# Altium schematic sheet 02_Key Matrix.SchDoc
size 464 x 203 mm
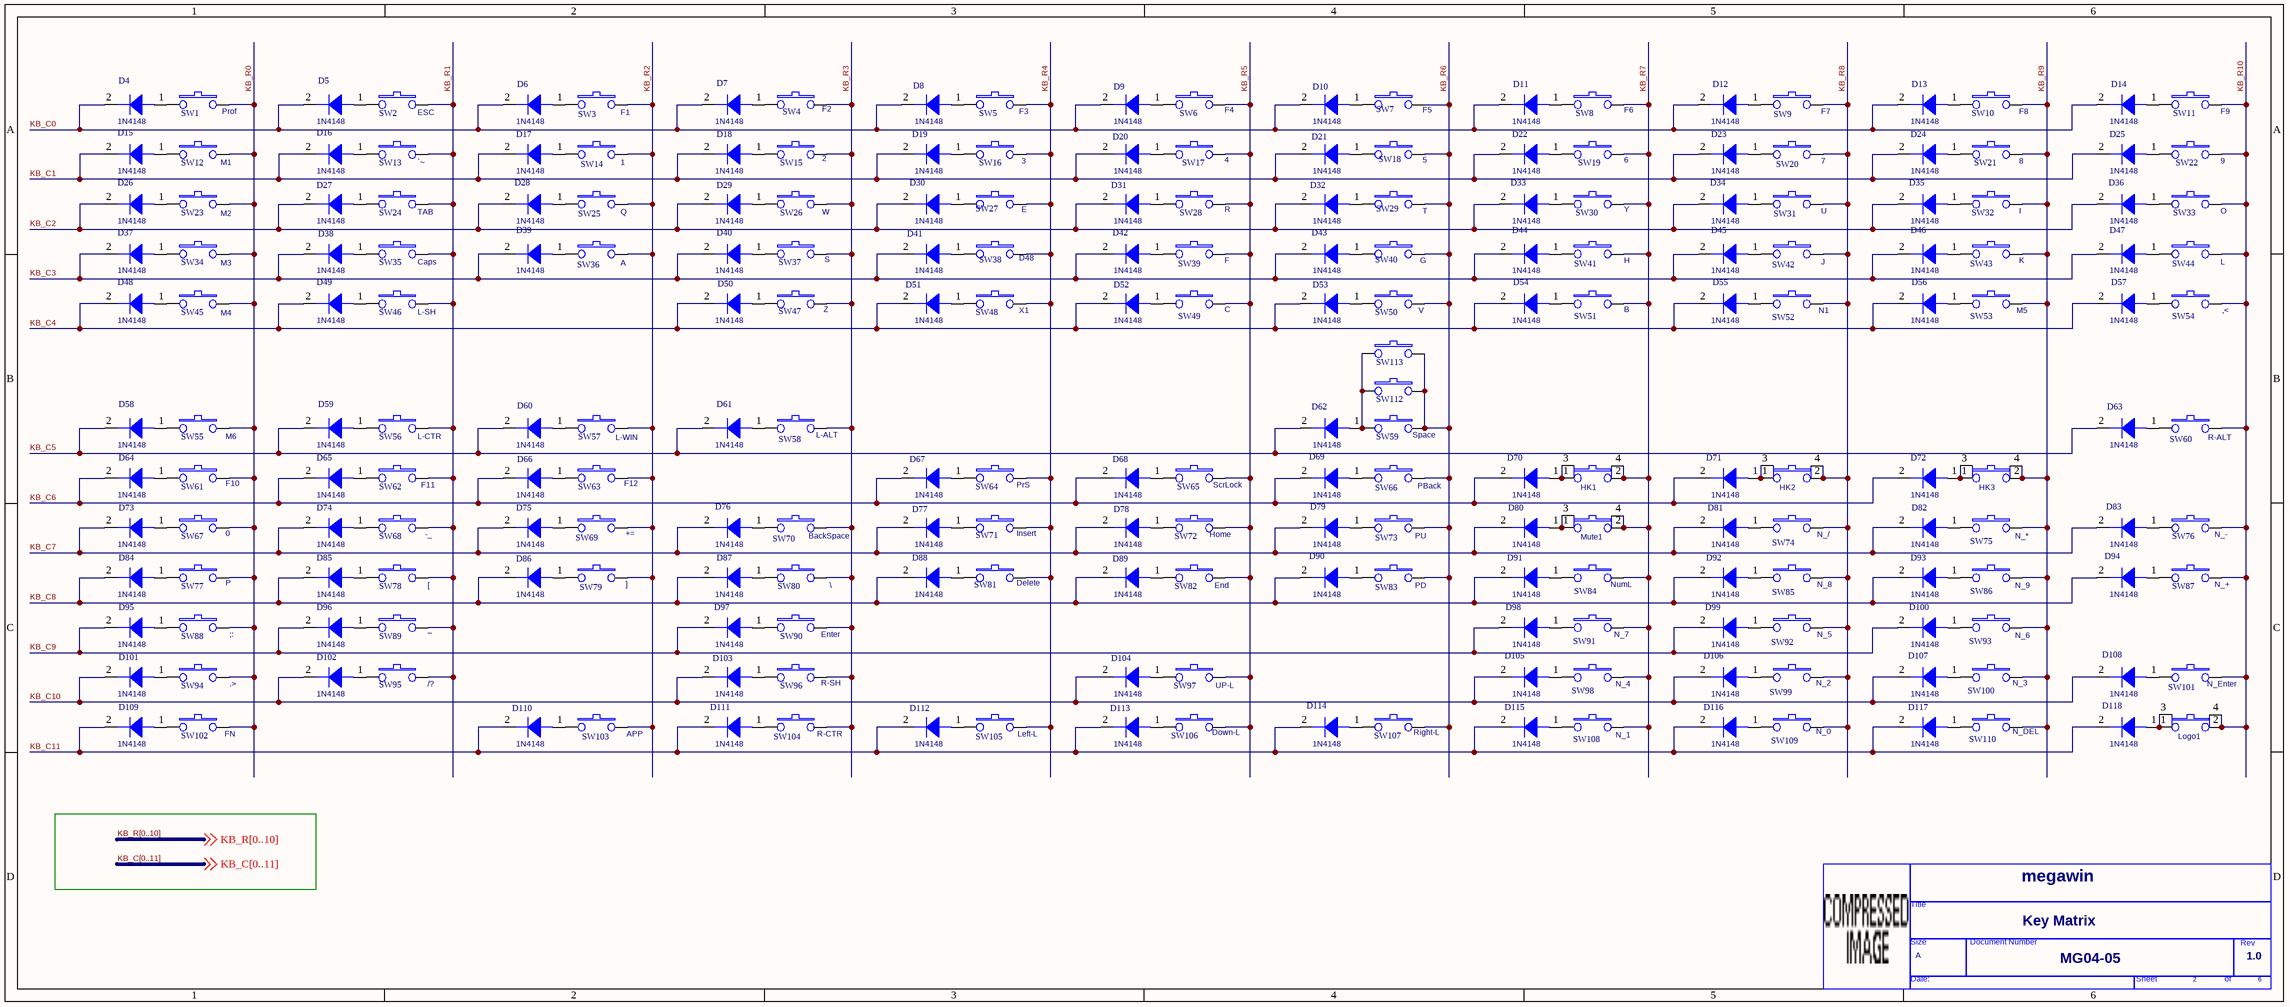
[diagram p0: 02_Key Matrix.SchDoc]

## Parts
*  OrgName: megawin  Doc: MG04-05  RevCode: 1.0  Title: Key Matrix  Page Size: A  Page Number: 2  Page Count: 6  (hidden comment: TitleBlock_MegaWin)  (graphical)
D4  1N4148  [DIODE_DO213AA]
D5  1N4148  [DIODE_DO213AA]
D6  1N4148  [DIODE_DO213AA]
D7  1N4148  [DIODE_DO213AA]
D8  1N4148  [DIODE_DO213AA]
D9  1N4148  [DIODE_DO213AA]
D10  1N4148  [DIODE_DO213AA]
D11  1N4148  [DIODE_DO213AA]
D12  1N4148  [DIODE_DO213AA]
D13  1N4148  [DIODE_DO213AA]
D14  1N4148  [DIODE_DO213AA]
D15  1N4148  [DIODE_DO213AA]
D16  1N4148  [DIODE_DO213AA]
D17  1N4148  [DIODE_DO213AA]
D18  1N4148  [DIODE_DO213AA]
D19  1N4148  [DIODE_DO213AA]
D20  1N4148  [DIODE_DO213AA]
D21  1N4148  [DIODE_DO213AA]
D22  1N4148  [DIODE_DO213AA]
D23  1N4148  [DIODE_DO213AA]
D24  1N4148  [DIODE_DO213AA]
D25  1N4148  [DIODE_DO213AA]
D26  1N4148  [DIODE_DO213AA]
D27  1N4148  [DIODE_DO213AA]
D28  1N4148  [DIODE_DO213AA]
D29  1N4148  [DIODE_DO213AA]
D30  1N4148  [DIODE_DO213AA]
D31  1N4148  [DIODE_DO213AA]
D32  1N4148  [DIODE_DO213AA]
D33  1N4148  [DIODE_DO213AA]
D34  1N4148  [DIODE_DO213AA]
D35  1N4148  [DIODE_DO213AA]
D36  1N4148  [DIODE_DO213AA]
D37  1N4148  [DIODE_DO213AA]
D38  1N4148  [DIODE_DO213AA]
D39  1N4148  [DIODE_DO213AA]
D40  1N4148  [DIODE_DO213AA]
D41  1N4148  [DIODE_DO213AA]
D42  1N4148  [DIODE_DO213AA]
D43  1N4148  [DIODE_DO213AA]
D44  1N4148  [DIODE_DO213AA]
D45  1N4148  [DIODE_DO213AA]
D46  1N4148  [DIODE_DO213AA]
D47  1N4148  [DIODE_DO213AA]
D48  1N4148  [DIODE_DO213AA]
D49  1N4148  [DIODE_DO213AA]
D50  1N4148  [DIODE_DO213AA]
D51  1N4148  [DIODE_DO213AA]
D52  1N4148  [DIODE_DO213AA]
D53  1N4148  [DIODE_DO213AA]
D54  1N4148  [DIODE_DO213AA]
D55  1N4148  [DIODE_DO213AA]
D56  1N4148  [DIODE_DO213AA]
D57  1N4148  [DIODE_DO213AA]
D58  1N4148  [DIODE_DO213AA]
D59  1N4148  [DIODE_DO213AA]
D60  1N4148  [DIODE_DO213AA]
D61  1N4148  [DIODE_DO213AA]
D62  1N4148  [DIODE_DO213AA]
D63  1N4148  [DIODE_DO213AA]
D64  1N4148  [DIODE_DO213AA]
D65  1N4148  [DIODE_DO213AA]
D66  1N4148  [DIODE_DO213AA]
D67  1N4148  [DIODE_DO213AA]
D68  1N4148  [DIODE_DO213AA]
D69  1N4148  [DIODE_DO213AA]
D70  1N4148  [DIODE_DO213AA]
D71  1N4148  [DIODE_DO213AA]
D72  1N4148  [DIODE_DO213AA]
D73  1N4148  [DIODE_DO213AA]
D74  1N4148  [DIODE_DO213AA]
D75  1N4148  [DIODE_DO213AA]
D76  1N4148  [DIODE_DO213AA]
D77  1N4148  [DIODE_DO213AA]
D78  1N4148  [DIODE_DO213AA]
D79  1N4148  [DIODE_DO213AA]
D80  1N4148  [DIODE_DO213AA]
D81  1N4148  [DIODE_DO213AA]
D82  1N4148  [DIODE_DO213AA]
D83  1N4148  [DIODE_DO213AA]
D84  1N4148  [DIODE_DO213AA]
D85  1N4148  [DIODE_DO213AA]
D86  1N4148  [DIODE_DO213AA]
D87  1N4148  [DIODE_DO213AA]
D88  1N4148  [DIODE_DO213AA]
D89  1N4148  [DIODE_DO213AA]
D90  1N4148  [DIODE_DO213AA]
D91  1N4148  [DIODE_DO213AA]
D92  1N4148  [DIODE_DO213AA]
D93  1N4148  [DIODE_DO213AA]
D94  1N4148  [DIODE_DO213AA]
D95  1N4148  [DIODE_DO213AA]
D96  1N4148  [DIODE_DO213AA]
D97  1N4148  [DIODE_DO213AA]
D98  1N4148  [DIODE_DO213AA]
D99  1N4148  [DIODE_DO213AA]
D100  1N4148  [DIODE_DO213AA]
D101  1N4148  [DIODE_DO213AA]
D102  1N4148  [DIODE_DO213AA]
D103  1N4148  [DIODE_DO213AA]
D104  1N4148  [DIODE_DO213AA]
D105  1N4148  [DIODE_DO213AA]
D106  1N4148  [DIODE_DO213AA]
D107  1N4148  [DIODE_DO213AA]
D108  1N4148  [DIODE_DO213AA]
D109  1N4148  [DIODE_DO213AA]
D110  1N4148  [DIODE_DO213AA]
D111  1N4148  [DIODE_DO213AA]
D112  1N4148  [DIODE_DO213AA]
D113  1N4148  [DIODE_DO213AA]
D114  1N4148  [DIODE_DO213AA]
D115  1N4148  [DIODE_DO213AA]
D116  1N4148  [DIODE_DO213AA]
D117  1N4148  [DIODE_DO213AA]
D118  1N4148  [DIODE_DO213AA]
HK1  SW-PB-4P  [SW-TACT-P4.5X6.5-Z6.2X6.2X5]  (value not drawn)
HK2  SW-PB-4P  [SW-TACT-P4.5X6.5-Z6.2X6.2X5]  (value not drawn)
HK3  SW-PB-4P  [SW-TACT-P4.5X6.5-Z6.2X6.2X5]  (value not drawn)
Logo1  SW-PB-4P  [SW-TACT-P4.5X6.5-Z6.2X6.2X5]  (value not drawn)
Mute1  SW-PB-4P  [SW-TACT-P4.5X6.5-Z6.2X6.2X5]  (value not drawn)
SW1  Function: Prof  [SW2_KS4B]  (hidden comment: SW_PB_SPST)
SW2  Function: ESC  [SW2_KS4B]  (hidden comment: SW_PB_SPST)
SW3  Function: F1  [SW2_KS4B]  (hidden comment: SW_PB_SPST)
SW4  Function: F2  [SW2_KS4B]  (hidden comment: SW_PB_SPST)
SW5  Function: F3  [SW2_KS4B]  (hidden comment: SW_PB_SPST)
SW6  Function: F4  [SW2_KS4B]  (hidden comment: SW_PB_SPST)
SW7  Function: F5  [SW2_KS4B]  (hidden comment: SW_PB_SPST)
SW8  Function: F6  [SW2_KS4B]  (hidden comment: SW_PB_SPST)
SW9  Function: F7  [SW2_KS4B]  (hidden comment: SW_PB_SPST)
SW10  Function: F8  [SW2_KS4B]  (hidden comment: SW_PB_SPST)
SW11  Function: F9  [SW2_KS4B]  (hidden comment: SW_PB_SPST)
SW12  Function: M1  [SW2_KS4B]  (hidden comment: SW_PB_SPST)
SW13  Function: `~  [SW2_KS4B]  (hidden comment: SW_PB_SPST)
SW14  Function: 1  [SW2_KS4B]  (hidden comment: SW_PB_SPST)
SW15  Function: 2  [SW2_KS4B]  (hidden comment: SW_PB_SPST)
SW16  Function: 3  [SW2_KS4B]  (hidden comment: SW_PB_SPST)
SW17  Function: 4  [SW2_KS4B]  (hidden comment: SW_PB_SPST)
SW18  Function: 5  [SW2_KS4B]  (hidden comment: SW_PB_SPST)
SW19  Function: 6  [SW2_KS4B]  (hidden comment: SW_PB_SPST)
SW20  Function: 7  [SW2_KS4B]  (hidden comment: SW_PB_SPST)
SW21  Function: 8  [SW2_KS4B]  (hidden comment: SW_PB_SPST)
SW22  Function: 9  [SW2_KS4B]  (hidden comment: SW_PB_SPST)
SW23  Function: M2  [SW2_KS4B]  (hidden comment: SW_PB_SPST)
SW24  Function: TAB  [SW2_KS4B]  (hidden comment: SW_PB_SPST)
SW25  Function: Q  [SW2_KS4B]  (hidden comment: SW_PB_SPST)
SW26  Function: W  [SW2_KS4B]  (hidden comment: SW_PB_SPST)
SW27  Function: E  [SW2_KS4B]  (hidden comment: SW_PB_SPST)
SW28  Function: R  [SW2_KS4B]  (hidden comment: SW_PB_SPST)
SW29  Function: T  [SW2_KS4B]  (hidden comment: SW_PB_SPST)
SW30  Function: Y  [SW2_KS4B]  (hidden comment: SW_PB_SPST)
SW31  Function: U  [SW2_KS4B]  (hidden comment: SW_PB_SPST)
SW32  Function: I  [SW2_KS4B]  (hidden comment: SW_PB_SPST)
SW33  Function: O  [SW2_KS4B]  (hidden comment: SW_PB_SPST)
SW34  Function: M3  [SW2_KS4B]  (hidden comment: SW_PB_SPST)
SW35  Function: Caps  [SW2_KS4B]  (hidden comment: SW_PB_SPST)
SW36  Function: A  [SW2_KS4B]  (hidden comment: SW_PB_SPST)
SW37  Function: S  [SW2_KS4B]  (hidden comment: SW_PB_SPST)
SW38  Function: D48  [SW2_KS4B]  (hidden comment: SW_PB_SPST)
SW39  Function: F  [SW2_KS4B]  (hidden comment: SW_PB_SPST)
SW40  Function: G  [SW2_KS4B]  (hidden comment: SW_PB_SPST)
SW41  Function: H  [SW2_KS4B]  (hidden comment: SW_PB_SPST)
SW42  Function: J  [SW2_KS4B]  (hidden comment: SW_PB_SPST)
SW43  Function: K  [SW2_KS4B]  (hidden comment: SW_PB_SPST)
SW44  Function: L  [SW2_KS4B]  (hidden comment: SW_PB_SPST)
SW45  Function: M4  [SW2_KS4B]  (hidden comment: SW_PB_SPST)
SW46  Function: L-SH  [SW2_KS4B]  (hidden comment: SW_PB_SPST)
SW47  Function: Z  [SW2_KS4B]  (hidden comment: SW_PB_SPST)
SW48  Function: X1  [SW2_KS4B]  (hidden comment: SW_PB_SPST)
SW49  Function: C  [SW2_KS4B]  (hidden comment: SW_PB_SPST)
SW50  Function: V  [SW2_KS4B]  (hidden comment: SW_PB_SPST)
SW51  Function: B  [SW2_KS4B]  (hidden comment: SW_PB_SPST)
SW52  Function: N1  [SW2_KS4B]  (hidden comment: SW_PB_SPST)
SW53  Function: M5  [SW2_KS4B]  (hidden comment: SW_PB_SPST)
SW54  Function: ,<  [SW2_KS4B]  (hidden comment: SW_PB_SPST)
SW55  Function: M6  [SW2_KS4B]  (hidden comment: SW_PB_SPST)
SW56  Function: L-CTR  [SW2_KS4B]  (hidden comment: SW_PB_SPST)
SW57  Function: L-WIN  [SW2_KS4B]  (hidden comment: SW_PB_SPST)
SW58  Function: L-ALT  [SW2_KS4B]  (hidden comment: SW_PB_SPST)
SW59  Function: Space  [SW2_KS4B]  (hidden comment: SW_PB_SPST)
SW60  Function: R-ALT  [SW2_KS4B]  (hidden comment: SW_PB_SPST)
SW61  Function: F10  [SW2_KS4B]  (hidden comment: SW_PB_SPST)
SW62  Function: F11  [SW2_KS4B]  (hidden comment: SW_PB_SPST)
SW63  Function: F12  [SW2_KS4B]  (hidden comment: SW_PB_SPST)
SW64  Function: PrS  [SW2_KS4B]  (hidden comment: SW_PB_SPST)
SW65  Function: ScrLock  [SW2_KS4B]  (hidden comment: SW_PB_SPST)
SW66  Function: PBack  [SW2_KS4B]  (hidden comment: SW_PB_SPST)
SW67  Function: 0  [SW2_KS4B]  (hidden comment: SW_PB_SPST)
SW68  Function: -_  [SW2_KS4B]  (hidden comment: SW_PB_SPST)
SW69  Function: +=  [SW2_KS4B]  (hidden comment: SW_PB_SPST)
SW70  Function: BackSpace  [SW2_KS4B]  (hidden comment: SW_PB_SPST)
SW71  Function: Insert  [SW2_KS4B]  (hidden comment: SW_PB_SPST)
SW72  Function: Home  [SW2_KS4B]  (hidden comment: SW_PB_SPST)
SW73  Function: PU  [SW2_KS4B]  (hidden comment: SW_PB_SPST)
SW74  Function: N_/  [SW2_KS4B]  (hidden comment: SW_PB_SPST)
SW75  Function: N_*  [SW2_KS4B]  (hidden comment: SW_PB_SPST)
SW76  Function: N_-  [SW2_KS4B]  (hidden comment: SW_PB_SPST)
SW77  Function: P  [SW2_KS4B]  (hidden comment: SW_PB_SPST)
SW78  Function: [  [SW2_KS4B]  (hidden comment: SW_PB_SPST)
SW79  Function: ]  [SW2_KS4B]  (hidden comment: SW_PB_SPST)
SW80  Function: \  [SW2_KS4B]  (hidden comment: SW_PB_SPST)
SW81  Function: Delete  [SW2_KS4B]  (hidden comment: SW_PB_SPST)
SW82  Function: End  [SW2_KS4B]  (hidden comment: SW_PB_SPST)
SW83  Function: PD  [SW2_KS4B]  (hidden comment: SW_PB_SPST)
SW84  Function: NumL  [SW2_KS4B]  (hidden comment: SW_PB_SPST)
SW85  Function: N_8  [SW2_KS4B]  (hidden comment: SW_PB_SPST)
SW86  Function: N_9  [SW2_KS4B]  (hidden comment: SW_PB_SPST)
SW87  Function: N_+  [SW2_KS4B]  (hidden comment: SW_PB_SPST)
SW88  Function: ;:  [SW2_KS4B]  (hidden comment: SW_PB_SPST)
SW89  Function: '"  [SW2_KS4B]  (hidden comment: SW_PB_SPST)
SW90  Function: Enter  [SW2_KS4B]  (hidden comment: SW_PB_SPST)
SW91  Function: N_7  [SW2_KS4B]  (hidden comment: SW_PB_SPST)
SW92  Function: N_5  [SW2_KS4B]  (hidden comment: SW_PB_SPST)
SW93  Function: N_6  [SW2_KS4B]  (hidden comment: SW_PB_SPST)
SW94  Function: .>  [SW2_KS4B]  (hidden comment: SW_PB_SPST)
SW95  Function: /?  [SW2_KS4B]  (hidden comment: SW_PB_SPST)
SW96  Function: R-SH  [SW2_KS4B]  (hidden comment: SW_PB_SPST)
SW97  Function: UP-L  [SW2_KS4B]  (hidden comment: SW_PB_SPST)
SW98  Function: N_4  [SW2_KS4B]  (hidden comment: SW_PB_SPST)
SW99  Function: N_2  [SW2_KS4B]  (hidden comment: SW_PB_SPST)
SW100  Function: N_3  [SW2_KS4B]  (hidden comment: SW_PB_SPST)
SW101  Function: N_Enter  [SW2_KS4B]  (hidden comment: SW_PB_SPST)
SW102  Function: FN  [SW2_KS4B]  (hidden comment: SW_PB_SPST)
SW103  Function: APP  [SW2_KS4B]  (hidden comment: SW_PB_SPST)
SW104  Function: R-CTR  [SW2_KS4B]  (hidden comment: SW_PB_SPST)
SW105  Function: Left-L  [SW2_KS4B]  (hidden comment: SW_PB_SPST)
SW106  Function: Down-L  [SW2_KS4B]  (hidden comment: SW_PB_SPST)
SW107  Function: Right-L  [SW2_KS4B]  (hidden comment: SW_PB_SPST)
SW108  Function: N_1  [SW2_KS4B]  (hidden comment: SW_PB_SPST)
SW109  Function: N_0  [SW2_KS4B]  (hidden comment: SW_PB_SPST)
SW110  Function: N_DEL  [SW2_KS4B]  (hidden comment: SW_PB_SPST)
SW112  SW_PB_SPST  [SW2_KS4B]  (value not drawn)
SW113  SW_PB_SPST  [SW2_KS4B]  (value not drawn)

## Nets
KB_C0: D4.2(C) D5.2(C) D6.2(C) D7.2(C) D8.2(C) D9.2(C) D10.2(C) D11.2(C) D12.2(C) D13.2(C) D14.2(C)
KB_C1: D15.2(C) D16.2(C) D17.2(C) D18.2(C) D19.2(C) D20.2(C) D21.2(C) D22.2(C) D23.2(C) D24.2(C) D25.2(C)
KB_C2: D26.2(C) D27.2(C) D28.2(C) D29.2(C) D30.2(C) D31.2(C) D32.2(C) D33.2(C) D34.2(C) D35.2(C) D36.2(C)
KB_C3: D37.2(C) D38.2(C) D39.2(C) D40.2(C) D41.2(C) D42.2(C) D43.2(C) D44.2(C) D45.2(C) D46.2(C) D47.2(C)
KB_C4: D48.2(C) D49.2(C) D50.2(C) D51.2(C) D52.2(C) D53.2(C) D54.2(C) D55.2(C) D56.2(C) D57.2(C)
KB_C5: D58.2(C) D59.2(C) D60.2(C) D61.2(C) D62.2(C) D63.2(C)
KB_C6: D64.2(C) D65.2(C) D66.2(C) D67.2(C) D68.2(C) D69.2(C) D70.2(C) D71.2(C) D72.2(C)
KB_C7: D73.2(C) D74.2(C) D75.2(C) D76.2(C) D77.2(C) D78.2(C) D79.2(C) D80.2(C) D81.2(C) D82.2(C) D83.2(C)
KB_C8: D84.2(C) D85.2(C) D86.2(C) D87.2(C) D88.2(C) D89.2(C) D90.2(C) D91.2(C) D92.2(C) D93.2(C) D94.2(C)
KB_C9: D95.2(C) D96.2(C) D97.2(C) D98.2(C) D99.2(C) D100.2(C)
KB_C10: D101.2(C) D102.2(C) D103.2(C) D104.2(C) D105.2(C) D106.2(C) D107.2(C) D108.2(C)
KB_C11: D109.2(C) D110.2(C) D111.2(C) D112.2(C) D113.2(C) D114.2(C) D115.2(C) D116.2(C) D117.2(C) D118.2(C)
KB_R0: SW1.2 SW12.2 SW23.2 SW34.2 SW45.2 SW55.2 SW61.2 SW67.2 SW77.2 SW88.2 SW94.2 SW102.2
KB_R1: SW2.2 SW13.2 SW24.2 SW35.2 SW46.2 SW56.2 SW62.2 SW68.2 SW78.2 SW89.2 SW95.2
KB_R2: SW3.2 SW14.2 SW25.2 SW36.2 SW57.2 SW63.2 SW69.2 SW79.2 SW103.2
KB_R3: SW4.2 SW15.2 SW26.2 SW37.2 SW47.2 SW58.2 SW70.2 SW80.2 SW90.2 SW96.2 SW104.2
KB_R4: SW5.2 SW16.2 SW27.2 SW38.2 SW48.2 SW64.2 SW71.2 SW81.2 SW105.2
KB_R5: SW6.2 SW17.2 SW28.2 SW39.2 SW49.2 SW65.2 SW72.2 SW82.2 SW97.2 SW106.2
KB_R6: SW7.2 SW18.2 SW29.2 SW40.2 SW50.2 SW59.2 SW66.2 SW73.2 SW83.2 SW107.2 SW112.2 SW113.2
KB_R7: HK1.2 HK1.4 Mute1.2 Mute1.4 SW8.2 SW19.2 SW30.2 SW41.2 SW51.2 SW84.2 SW91.2 SW98.2 SW108.2
KB_R8: HK2.2 HK2.4 SW9.2 SW20.2 SW31.2 SW42.2 SW52.2 SW74.2 SW85.2 SW92.2 SW99.2 SW109.2
KB_R9: HK3.2 HK3.4 SW10.2 SW21.2 SW32.2 SW43.2 SW53.2 SW75.2 SW86.2 SW93.2 SW100.2 SW110.2
KB_R10: Logo1.2 Logo1.4 SW11.2 SW22.2 SW33.2 SW44.2 SW54.2 SW60.2 SW76.2 SW87.2 SW101.2
NetD4_1: D4.1(A) SW1.1
NetD5_1: D5.1(A) SW2.1
NetD6_1: D6.1(A) SW3.1
NetD7_1: D7.1(A) SW4.1
NetD8_1: D8.1(A) SW5.1
NetD9_1: D9.1(A) SW6.1
NetD10_1: D10.1(A) SW7.1
NetD11_1: D11.1(A) SW8.1
NetD12_1: D12.1(A) SW9.1
NetD13_1: D13.1(A) SW10.1
NetD14_1: D14.1(A) SW11.1
NetD15_1: D15.1(A) SW12.1
NetD16_1: D16.1(A) SW13.1
NetD17_1: D17.1(A) SW14.1
NetD18_1: D18.1(A) SW15.1
NetD19_1: D19.1(A) SW16.1
NetD20_1: D20.1(A) SW17.1
NetD21_1: D21.1(A) SW18.1
NetD22_1: D22.1(A) SW19.1
NetD23_1: D23.1(A) SW20.1
NetD24_1: D24.1(A) SW21.1
NetD25_1: D25.1(A) SW22.1
NetD26_1: D26.1(A) SW23.1
NetD27_1: D27.1(A) SW24.1
NetD28_1: D28.1(A) SW25.1
NetD29_1: D29.1(A) SW26.1
NetD30_1: D30.1(A) SW27.1
NetD31_1: D31.1(A) SW28.1
NetD32_1: D32.1(A) SW29.1
NetD33_1: D33.1(A) SW30.1
NetD34_1: D34.1(A) SW31.1
NetD35_1: D35.1(A) SW32.1
NetD36_1: D36.1(A) SW33.1
NetD37_1: D37.1(A) SW34.1
NetD38_1: D38.1(A) SW35.1
NetD39_1: D39.1(A) SW36.1
NetD40_1: D40.1(A) SW37.1
NetD41_1: D41.1(A) SW38.1
NetD42_1: D42.1(A) SW39.1
NetD43_1: D43.1(A) SW40.1
NetD44_1: D44.1(A) SW41.1
NetD45_1: D45.1(A) SW42.1
NetD46_1: D46.1(A) SW43.1
NetD47_1: D47.1(A) SW44.1
NetD48_1: D48.1(A) SW45.1
NetD49_1: D49.1(A) SW46.1
NetD50_1: D50.1(A) SW47.1
NetD51_1: D51.1(A) SW48.1
NetD52_1: D52.1(A) SW49.1
NetD53_1: D53.1(A) SW50.1
NetD54_1: D54.1(A) SW51.1
NetD55_1: D55.1(A) SW52.1
NetD56_1: D56.1(A) SW53.1
NetD57_1: D57.1(A) SW54.1
NetD58_1: D58.1(A) SW55.1
NetD59_1: D59.1(A) SW56.1
NetD60_1: D60.1(A) SW57.1
NetD61_1: D61.1(A) SW58.1
NetD62_1: D62.1(A) SW59.1 SW112.1 SW113.1
NetD63_1: D63.1(A) SW60.1
NetD64_1: D64.1(A) SW61.1
NetD65_1: D65.1(A) SW62.1
NetD66_1: D66.1(A) SW63.1
NetD67_1: D67.1(A) SW64.1
NetD68_1: D68.1(A) SW65.1
NetD69_1: D69.1(A) SW66.1
NetD70_1: D70.1(A) HK1.1 HK1.3
NetD71_1: D71.1(A) HK2.1 HK2.3
NetD72_1: D72.1(A) HK3.1 HK3.3
NetD73_1: D73.1(A) SW67.1
NetD74_1: D74.1(A) SW68.1
NetD75_1: D75.1(A) SW69.1
NetD76_1: D76.1(A) SW70.1
NetD77_1: D77.1(A) SW71.1
NetD78_1: D78.1(A) SW72.1
NetD79_1: D79.1(A) SW73.1
NetD80_1: D80.1(A) Mute1.1 Mute1.3
NetD81_1: D81.1(A) SW74.1
NetD82_1: D82.1(A) SW75.1
NetD83_1: D83.1(A) SW76.1
NetD84_1: D84.1(A) SW77.1
NetD85_1: D85.1(A) SW78.1
NetD86_1: D86.1(A) SW79.1
NetD87_1: D87.1(A) SW80.1
NetD88_1: D88.1(A) SW81.1
NetD89_1: D89.1(A) SW82.1
NetD90_1: D90.1(A) SW83.1
NetD91_1: D91.1(A) SW84.1
NetD92_1: D92.1(A) SW85.1
NetD93_1: D93.1(A) SW86.1
NetD94_1: D94.1(A) SW87.1
NetD95_1: D95.1(A) SW88.1
NetD96_1: D96.1(A) SW89.1
NetD97_1: D97.1(A) SW90.1
NetD98_1: D98.1(A) SW91.1
NetD99_1: D99.1(A) SW92.1
NetD100_1: D100.1(A) SW93.1
NetD101_1: D101.1(A) SW94.1
NetD102_1: D102.1(A) SW95.1
NetD103_1: D103.1(A) SW96.1
NetD104_1: D104.1(A) SW97.1
NetD105_1: D105.1(A) SW98.1
NetD106_1: D106.1(A) SW99.1
NetD107_1: D107.1(A) SW100.1
NetD108_1: D108.1(A) SW101.1
NetD109_1: D109.1(A) SW102.1
NetD110_1: D110.1(A) SW103.1
NetD111_1: D111.1(A) SW104.1
NetD112_1: D112.1(A) SW105.1
NetD113_1: D113.1(A) SW106.1
NetD114_1: D114.1(A) SW107.1
NetD115_1: D115.1(A) SW108.1
NetD116_1: D116.1(A) SW109.1
NetD117_1: D117.1(A) SW110.1
NetD118_1: D118.1(A) Logo1.1 Logo1.3

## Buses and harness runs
bus KB_C[0..11]
bus KB_R[0..10]

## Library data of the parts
D4-D118 = DIODE
HK1-HK3 Logo1 Mute1 = SW-PB-4P2
SW1-SW110 = SW-PB-2P-KB
SW112 SW113 = SW-PB-2P-KB: Function: Space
